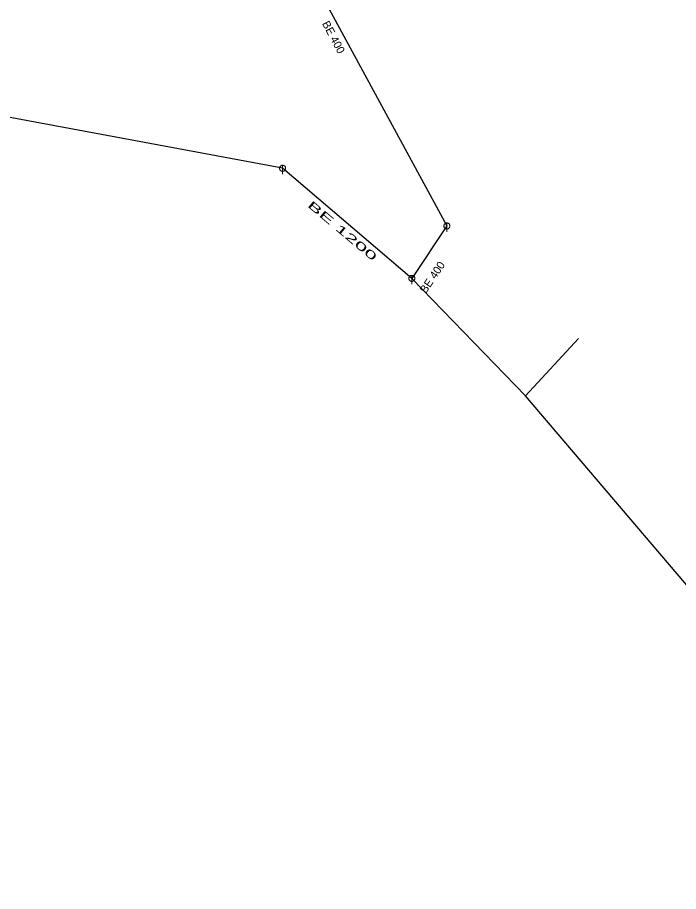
# Model space of a CAD drawing. Extents: x -687468 to -685917, y -974192 to -973456.
# Drawn here: x -686142.7 to -686087.6, y -974019.8 to -973947 of the extents above; entities that cross this region are included whole.
import ezdxf
from ezdxf.enums import TextEntityAlignment as Align

# ---------------------------------------------------------------- set-up
doc = ezdxf.new("R2010")
doc.units = 0
doc.header["$LTSCALE"] = 0.27
for name, color, linetype, lineweight in [('1', 7, 'Continuous', 13), ('11', 7, 'Continuous', 13), ('14', 7, 'Continuous', 25), ('22', 7, 'Continuous', 13)]:
    doc.layers.add(name, color=color, linetype=linetype, lineweight=lineweight)

msp = doc.modelspace()

# ---------------------------------------------------------------- linework, layer by layer
at = {"layer": '11'}
msp.add_line((-686095.969, -973973.738), (-686100.367, -973978.502), dxfattribs=at)
at = {"layer": '14'}
for p, q in [((-686120.612, -973959.55), (-686172.417, -973949.902)), ((-686109.848, -973968.717), (-686120.612, -973959.55)), ((-686106.927, -973964.355), (-686109.848, -973968.717))]:
    msp.add_line(p, q, dxfattribs=at)
for points in [[(-686124.153, -973921.386), (-686122.535, -973935.572), (-686106.927, -973964.355)], [(-686065.207, -974019.789), (-686100.367, -973978.502), (-686109.848, -973968.717)]]:
    msp.add_lwpolyline(points, dxfattribs=at)
at = {"layer": '22'}
for p, q in [((-686120.611, -973959.298), (-686120.612, -973960.042)), ((-686106.926, -973964.103), (-686106.927, -973964.847)), ((-686109.847, -973968.465), (-686109.848, -973969.208))]:
    msp.add_line(p, q, dxfattribs=at)
for points in [[(-686120.36, -973959.55), (-686120.361, -973959.524), (-686120.365, -973959.498), (-686120.371, -973959.472), (-686120.381, -973959.448), (-686120.393, -973959.424), (-686120.407, -973959.402), (-686120.424, -973959.381), (-686120.442, -973959.363), (-686120.463, -973959.346), (-686120.485, -973959.332), (-686120.509, -973959.32), (-686120.533, -973959.31), (-686120.559, -973959.304), (-686120.585, -973959.3), (-686120.611, -973959.298), (-686120.637, -973959.299), (-686120.663, -973959.303), (-686120.689, -973959.309), (-686120.714, -973959.319), (-686120.737, -973959.331), (-686120.759, -973959.345), (-686120.78, -973959.362), (-686120.798, -973959.38), (-686120.815, -973959.401), (-686120.829, -973959.423), (-686120.841, -973959.447), (-686120.851, -973959.471), (-686120.858, -973959.497), (-686120.862, -973959.523), (-686120.864, -973959.549), (-686120.863, -973959.575), (-686120.859, -973959.601), (-686120.852, -973959.627), (-686120.842, -973959.652), (-686120.83, -973959.675), (-686120.816, -973959.697), (-686120.799, -973959.718), (-686120.781, -973959.736), (-686120.76, -973959.753), (-686120.738, -973959.767), (-686120.715, -973959.779), (-686120.69, -973959.789), (-686120.664, -973959.796), (-686120.638, -973959.8), (-686120.612, -973959.802), (-686120.586, -973959.801), (-686120.56, -973959.797), (-686120.534, -973959.79), (-686120.51, -973959.78), (-686120.486, -973959.768), (-686120.464, -973959.754), (-686120.443, -973959.737), (-686120.425, -973959.719), (-686120.408, -973959.698), (-686120.394, -973959.676), (-686120.382, -973959.653), (-686120.372, -973959.628), (-686120.366, -973959.602), (-686120.362, -973959.576)], [(-686106.675, -973964.355), (-686106.676, -973964.329), (-686106.68, -973964.303), (-686106.686, -973964.277), (-686106.696, -973964.253), (-686106.708, -973964.229), (-686106.722, -973964.207), (-686106.739, -973964.186), (-686106.757, -973964.168), (-686106.778, -973964.151), (-686106.8, -973964.137), (-686106.824, -973964.125), (-686106.848, -973964.115), (-686106.874, -973964.109), (-686106.9, -973964.105), (-686106.926, -973964.103), (-686106.952, -973964.104), (-686106.978, -973964.108), (-686107.004, -973964.114), (-686107.029, -973964.124), (-686107.052, -973964.136), (-686107.074, -973964.15), (-686107.095, -973964.167), (-686107.113, -973964.185), (-686107.13, -973964.206), (-686107.144, -973964.228), (-686107.156, -973964.252), (-686107.166, -973964.276), (-686107.173, -973964.302), (-686107.177, -973964.328), (-686107.179, -973964.354), (-686107.178, -973964.38), (-686107.174, -973964.406), (-686107.167, -973964.432), (-686107.157, -973964.457), (-686107.145, -973964.48), (-686107.131, -973964.502), (-686107.114, -973964.523), (-686107.096, -973964.541), (-686107.075, -973964.558), (-686107.053, -973964.572), (-686107.03, -973964.584), (-686107.005, -973964.594), (-686106.979, -973964.601), (-686106.953, -973964.605), (-686106.927, -973964.607), (-686106.901, -973964.606), (-686106.875, -973964.602), (-686106.849, -973964.595), (-686106.825, -973964.585), (-686106.801, -973964.573), (-686106.779, -973964.559), (-686106.758, -973964.542), (-686106.74, -973964.524), (-686106.723, -973964.503), (-686106.709, -973964.481), (-686106.697, -973964.458), (-686106.687, -973964.433), (-686106.681, -973964.407), (-686106.677, -973964.381)], [(-686109.596, -973968.717), (-686109.597, -973968.691), (-686109.601, -973968.665), (-686109.607, -973968.639), (-686109.617, -973968.615), (-686109.629, -973968.591), (-686109.643, -973968.569), (-686109.66, -973968.548), (-686109.678, -973968.53), (-686109.699, -973968.513), (-686109.721, -973968.499), (-686109.745, -973968.487), (-686109.769, -973968.477), (-686109.795, -973968.471), (-686109.821, -973968.467), (-686109.847, -973968.465), (-686109.873, -973968.466), (-686109.899, -973968.47), (-686109.925, -973968.476), (-686109.95, -973968.486), (-686109.973, -973968.498), (-686109.995, -973968.512), (-686110.016, -973968.529), (-686110.034, -973968.547), (-686110.051, -973968.568), (-686110.065, -973968.59), (-686110.077, -973968.614), (-686110.087, -973968.638), (-686110.094, -973968.664), (-686110.098, -973968.69), (-686110.1, -973968.716), (-686110.099, -973968.742), (-686110.095, -973968.768), (-686110.088, -973968.794), (-686110.078, -973968.819), (-686110.066, -973968.842), (-686110.052, -973968.864), (-686110.035, -973968.885), (-686110.017, -973968.903), (-686109.996, -973968.92), (-686109.974, -973968.934), (-686109.951, -973968.946), (-686109.926, -973968.956), (-686109.9, -973968.963), (-686109.874, -973968.967), (-686109.848, -973968.968), (-686109.822, -973968.968), (-686109.796, -973968.964), (-686109.77, -973968.957), (-686109.746, -973968.947), (-686109.722, -973968.935), (-686109.7, -973968.921), (-686109.679, -973968.904), (-686109.661, -973968.886), (-686109.644, -973968.865), (-686109.63, -973968.843), (-686109.618, -973968.82), (-686109.608, -973968.795), (-686109.602, -973968.769), (-686109.598, -973968.743)]]:
    msp.add_lwpolyline(points, close=True, dxfattribs=at)

# ---------------------------------------------------------------- texts
at = {"layer": '1'}
for rotation, p in [(298, (-686116.657, -973948.785)), (56, (-686107.86, -973968.811))]:
    msp.add_text('BE 400', height=0.6667, rotation=rotation, dxfattribs=at).set_placement(p, align=Align.CENTER)
at = {"layer": '1', "width": 2.1}
msp.add_text('BE 1200 ', height=0.6667, rotation=320, dxfattribs=at).set_placement((-686115.643, -973965.172), align=Align.CENTER)

doc.saveas('drawing.dxf')
